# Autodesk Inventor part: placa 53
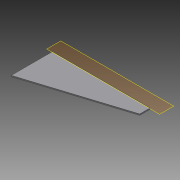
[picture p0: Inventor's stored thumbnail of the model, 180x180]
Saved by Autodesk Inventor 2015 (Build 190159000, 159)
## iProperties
Created: 2015-04
Part Number: placa 53
Material: Generic
Document SubType Name: Modeling
Designer: suporte
Density: 1 g/cm^3
Appearance: Default
Author: suporte
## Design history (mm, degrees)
workplane "Work Plane1"
sketch "Sketch1"
  geometry: L1 (-500, -62.5)-(500, -62.5) reference; L2 (-500, -462.5)-(-500, 62.5) reference; L3 (450, -62.5)-(450, -162.5); L4 (450, -162.5)-(-500, -462.5); L5 (450, -62.5)-(-500, -62.5); L6 (-500, -62.5)-(-500, -462.5); 1 further point
  constraints: 8 end point, 1 collinear, 1 perpendicular, 1 point on line, 1 vertical
  dimensions: "d0" = 100 distance of L3.start L3.end; "d1" = 950 distance from line of L2 L3.end
extrude "Extrusion1" new body sketch "Sketch1" distance "d2" = 12.5; taper "d3" = 0 deg
body "Solid1"
node "Reference1"
node "Reference2"
